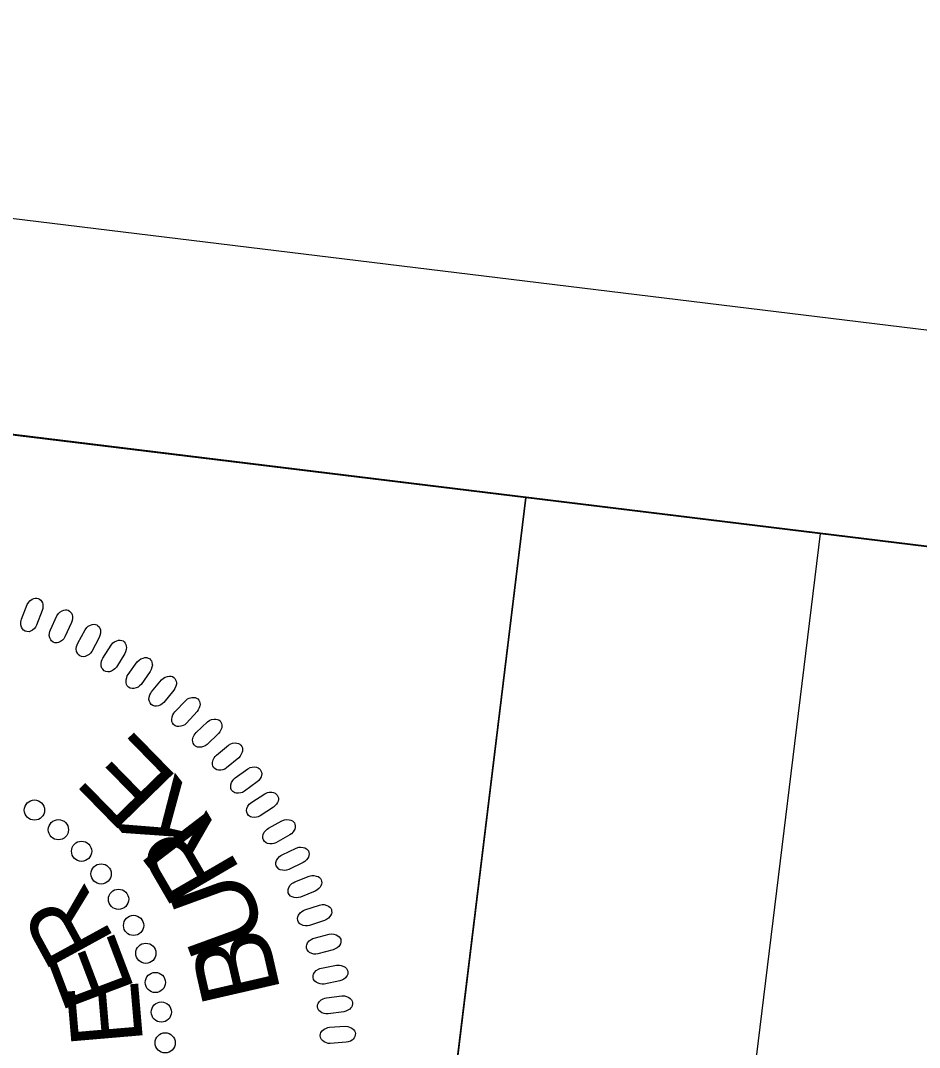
# Model space of a CAD drawing. Extents: x 480792 to 482083, y 490046 to 491850.
# Drawn here: x 481125.1 to 481196.3, y 491768.8 to 491850.2 of the extents above; entities that cross this region are included whole.
import ezdxf

# ---------------------------------------------------------------- set-up
doc = ezdxf.new("R2010")
doc.units = 0
for name, color, linetype in [('Sheet PE Seal Cell', 7, 'Continuous'), ('Sheet Plan CELL', 7, 'Continuous'), ('Sheet Plot Border Outside CELL', 7, 'Continuous'), ('Sheet Sticker Exception Certification CELL', 7, 'Continuous')]:
    doc.layers.add(name, color=color, linetype=linetype)

msp = doc.modelspace()

# ---------------------------------------------------------------- linework, layer by layer
at = {"layer": 'Sheet PE Seal Cell'}
for points in [[(481125.185, 491802.736), (481125.632, 491803.878), (481125.747, 491804.069), (481125.846, 491804.18), (481126.013, 491804.297), (481126.143, 491804.363), (481126.277, 491804.397), (481126.388, 491804.396), (481126.5, 491804.373), (481126.597, 491804.315), (481126.698, 491804.242), (481126.774, 491804.149), (481126.834, 491804.018), (481126.861, 491803.922), (481126.869, 491803.758), (481126.86, 491803.569), (481126.823, 491803.412), (481126.371, 491802.239), (481126.288, 491802.089), (481126.196, 491801.976), (481126.054, 491801.86), (481125.899, 491801.771), (481125.78, 491801.732), (481125.611, 491801.734), (481125.464, 491801.769), (481125.34, 491801.861), (481125.261, 491801.946), (481125.178, 491802.085), (481125.129, 491802.286), (481125.132, 491802.479), (481125.152, 491802.609)], [(481127.464, 491801.88), (481127.983, 491802.993), (481128.109, 491803.176), (481128.215, 491803.281), (481128.389, 491803.387), (481128.523, 491803.445), (481128.659, 491803.47), (481128.77, 491803.462), (481128.88, 491803.433), (481128.973, 491803.367), (481129.069, 491803.289), (481129.139, 491803.192), (481129.191, 491803.056), (481129.212, 491802.959), (481129.209, 491802.795), (481129.188, 491802.607), (481129.141, 491802.453), (481128.617, 491801.311), (481128.525, 491801.167), (481128.425, 491801.059), (481128.277, 491800.952), (481128.116, 491800.873), (481127.995, 491800.841), (481127.827, 491800.854), (481127.683, 491800.899), (481127.565, 491800.998), (481127.491, 491801.088), (481127.417, 491801.231), (481127.381, 491801.436), (481127.396, 491801.627), (481127.423, 491801.757)], [(481129.629, 491800.809), (481130.216, 491801.886), (481130.353, 491802.061), (481130.466, 491802.159), (481130.646, 491802.254), (481130.784, 491802.304), (481130.92, 491802.32), (481131.031, 491802.305), (481131.139, 491802.269), (481131.228, 491802.198), (481131.319, 491802.114), (481131.382, 491802.012), (481131.426, 491801.874), (481131.441, 491801.775), (481131.428, 491801.612), (481131.395, 491801.425), (481131.338, 491801.275), (481130.743, 491800.168), (481130.642, 491800.03), (481130.536, 491799.929), (481130.381, 491799.832), (481130.216, 491799.762), (481130.092, 491799.738), (481129.926, 491799.761), (481129.785, 491799.815), (481129.673, 491799.922), (481129.605, 491800.016), (481129.541, 491800.164), (481129.518, 491800.37), (481129.544, 491800.561), (481129.58, 491800.688)], [(481131.619, 491799.637), (481132.272, 491800.675), (481132.421, 491800.841), (481132.539, 491800.932), (481132.725, 491801.015), (481132.865, 491801.057), (481133.003, 491801.064), (481133.112, 491801.042), (481133.218, 491800.999), (481133.302, 491800.923), (481133.387, 491800.833), (481133.444, 491800.727), (481133.479, 491800.587), (481133.488, 491800.488), (481133.465, 491800.325), (481133.42, 491800.142), (481133.354, 491799.995), (481132.691, 491798.927), (481132.582, 491798.795), (481132.469, 491798.701), (481132.308, 491798.614), (481132.139, 491798.556), (481132.015, 491798.54), (481131.85, 491798.573), (481131.712, 491798.636), (481131.607, 491798.749), (481131.545, 491798.847), (481131.49, 491798.999), (481131.48, 491799.206), (481131.519, 491799.394), (481131.562, 491799.519)], [(481133.623, 491798.336), (481134.341, 491799.331), (481134.499, 491799.487), (481134.623, 491799.57), (481134.814, 491799.642), (481134.957, 491799.674), (481135.094, 491799.673), (481135.202, 491799.644), (481135.305, 491799.595), (481135.385, 491799.513), (481135.464, 491799.419), (481135.513, 491799.31), (481135.54, 491799.167), (481135.542, 491799.068), (481135.509, 491798.907), (481135.452, 491798.726), (481135.378, 491798.584), (481134.649, 491797.559), (481134.532, 491797.435), (481134.414, 491797.348), (481134.248, 491797.272), (481134.075, 491797.223), (481133.95, 491797.216), (481133.788, 491797.259), (481133.654, 491797.33), (481133.556, 491797.45), (481133.501, 491797.552), (481133.456, 491797.707), (481133.458, 491797.914), (481133.509, 491798.1), (481133.56, 491798.222)], [(481135.483, 491796.963), (481136.261, 491797.912), (481136.429, 491798.057), (481136.558, 491798.133), (481136.752, 491798.192), (481136.897, 491798.216), (481137.035, 491798.206), (481137.14, 491798.17), (481137.24, 491798.114), (481137.314, 491798.028), (481137.388, 491797.929), (481137.43, 491797.816), (481137.448, 491797.673), (481137.444, 491797.573), (481137.4, 491797.415), (481137.333, 491797.238), (481137.249, 491797.1), (481136.457, 491796.124), (481136.332, 491796.008), (481136.209, 491795.929), (481136.039, 491795.862), (481135.863, 491795.825), (481135.738, 491795.825), (481135.578, 491795.878), (481135.45, 491795.958), (481135.36, 491796.084), (481135.311, 491796.189), (481135.275, 491796.346), (481135.291, 491796.553), (481135.353, 491796.735), (481135.412, 491796.854)], [(481137.319, 491795.368), (481138.155, 491796.265), (481138.332, 491796.4), (481138.465, 491796.468), (481138.663, 491796.515), (481138.809, 491796.529), (481138.946, 491796.511), (481139.049, 491796.469), (481139.144, 491796.407), (481139.213, 491796.316), (481139.28, 491796.212), (481139.316, 491796.098), (481139.324, 491795.953), (481139.314, 491795.854), (481139.261, 491795.698), (481139.182, 491795.526), (481139.09, 491795.394), (481138.239, 491794.47), (481138.107, 491794.361), (481137.979, 491794.29), (481137.805, 491794.234), (481137.627, 491794.208), (481137.502, 491794.216), (481137.346, 491794.279), (481137.223, 491794.367), (481137.141, 491794.498), (481137.098, 491794.606), (481137.073, 491794.766), (481137.101, 491794.971), (481137.175, 491795.148), (481137.241, 491795.263)], [(481139.015, 491793.746), (481139.906, 491794.589), (481140.091, 491794.712), (481140.228, 491794.771), (481140.429, 491794.806), (481140.575, 491794.811), (481140.71, 491794.784), (481140.811, 491794.735), (481140.902, 491794.667), (481140.964, 491794.572), (481141.025, 491794.465), (481141.054, 491794.348), (481141.053, 491794.203), (481141.036, 491794.105), (481140.974, 491793.953), (481140.885, 491793.787), (481140.784, 491793.661), (481139.877, 491792.791), (481139.738, 491792.691), (481139.605, 491792.628), (481139.429, 491792.584), (481139.25, 491792.569), (481139.125, 491792.585), (481138.973, 491792.657), (481138.857, 491792.753), (481138.783, 491792.889), (481138.747, 491792.999), (481138.732, 491793.159), (481138.773, 491793.363), (481138.857, 491793.536), (481138.931, 491793.646)], [(481140.619, 491791.944), (481141.562, 491792.729), (481141.754, 491792.841), (481141.895, 491792.891), (481142.097, 491792.913), (481142.243, 491792.908), (481142.376, 491792.873), (481142.474, 491792.819), (481142.561, 491792.745), (481142.618, 491792.646), (481142.671, 491792.535), (481142.693, 491792.417), (481142.682, 491792.272), (481142.66, 491792.175), (481142.588, 491792.028), (481142.488, 491791.867), (481142.38, 491791.747), (481141.42, 491790.937), (481141.275, 491790.846), (481141.138, 491790.791), (481140.959, 491790.758), (481140.781, 491790.754), (481140.657, 491790.778), (481140.51, 491790.859), (481140.399, 491790.963), (481140.334, 491791.103), (481140.306, 491791.215), (481140.3, 491791.377), (481140.354, 491791.576), (481140.449, 491791.744), (481140.529, 491791.849)], [(481142.105, 491790.138), (481143.095, 491790.863), (481143.294, 491790.963), (481143.438, 491791.003), (481143.641, 491791.013), (481143.787, 491790.999), (481143.917, 491790.955), (481144.011, 491790.895), (481144.094, 491790.816), (481144.144, 491790.714), (481144.19, 491790.6), (481144.204, 491790.48), (481144.185, 491790.337), (481144.156, 491790.241), (481144.075, 491790.099), (481143.966, 491789.944), (481143.85, 491789.832), (481142.841, 491789.083), (481142.691, 491789.001), (481142.551, 491788.955), (481142.37, 491788.933), (481142.191, 491788.941), (481142.069, 491788.973), (481141.928, 491789.063), (481141.824, 491789.173), (481141.768, 491789.316), (481141.746, 491789.43), (481141.751, 491789.592), (481141.817, 491789.788), (481141.923, 491789.949), (481142.009, 491790.049)], [(481143.413, 491788.233), (481144.447, 491788.894), (481144.651, 491788.981), (481144.797, 491789.012), (481145.001, 491789.01), (481145.145, 491788.987), (481145.273, 491788.935), (481145.363, 491788.869), (481145.44, 491788.785), (481145.483, 491788.68), (481145.523, 491788.563), (481145.529, 491788.443), (481145.501, 491788.301), (481145.467, 491788.207), (481145.377, 491788.07), (481145.257, 491787.923), (481145.136, 491787.818), (481144.081, 491787.134), (481143.926, 491787.062), (481143.784, 491787.025), (481143.602, 491787.014), (481143.424, 491787.033), (481143.304, 491787.072), (481143.169, 491787.172), (481143.071, 491787.287), (481143.025, 491787.434), (481143.01, 491787.55), (481143.026, 491787.711), (481143.104, 491787.902), (481143.219, 491788.056), (481143.312, 491788.151)], [(481144.736, 491786.151), (481145.809, 491786.746), (481146.019, 491786.819), (481146.166, 491786.843), (481146.369, 491786.826), (481146.512, 491786.794), (481146.637, 491786.735), (481146.722, 491786.663), (481146.793, 491786.574), (481146.83, 491786.467), (481146.862, 491786.348), (481146.862, 491786.227), (481146.824, 491786.087), (481146.784, 491785.996), (481146.685, 491785.864), (481146.557, 491785.725), (481146.429, 491785.628), (481145.334, 491785.012), (481145.174, 491784.95), (481145.031, 491784.922), (481144.848, 491784.922), (481144.671, 491784.952), (481144.554, 491784.999), (481144.426, 491785.107), (481144.336, 491785.228), (481144.298, 491785.378), (481144.291, 491785.494), (481144.316, 491785.653), (481144.407, 491785.84), (481144.531, 491785.987), (481144.63, 491786.075)], [(481145.819, 491784.06), (481146.927, 491784.587), (481147.141, 491784.647), (481147.29, 491784.66), (481147.491, 491784.632), (481147.632, 491784.591), (481147.752, 491784.524), (481147.833, 491784.447), (481147.9, 491784.354), (481147.929, 491784.244), (481147.954, 491784.123), (481147.945, 491784.003), (481147.9, 491783.866), (481147.853, 491783.777), (481147.747, 491783.652), (481147.61, 491783.521), (481147.476, 491783.432), (481146.344, 491782.887), (481146.181, 491782.834), (481146.036, 491782.815), (481145.853, 491782.827), (481145.679, 491782.868), (481145.566, 491782.922), (481145.444, 491783.038), (481145.362, 491783.165), (481145.333, 491783.317), (481145.334, 491783.433), (481145.369, 491783.59), (481145.471, 491783.771), (481145.604, 491783.909), (481145.709, 491783.991)], [(481146.821, 491781.904), (481147.96, 491782.36), (481148.177, 491782.407), (481148.327, 491782.41), (481148.526, 491782.369), (481148.664, 491782.32), (481148.779, 491782.245), (481148.855, 491782.163), (481148.916, 491782.066), (481148.939, 491781.955), (481148.955, 491781.833), (481148.939, 491781.714), (481148.885, 491781.58), (481148.833, 491781.494), (481148.719, 491781.376), (481148.575, 491781.253), (481148.435, 491781.174), (481147.271, 491780.7), (481147.106, 491780.657), (481146.959, 491780.647), (481146.778, 491780.671), (481146.607, 491780.723), (481146.496, 491780.784), (481146.382, 491780.907), (481146.308, 491781.039), (481146.29, 491781.192), (481146.297, 491781.308), (481146.342, 491781.463), (481146.455, 491781.637), (481146.597, 491781.767), (481146.706, 491781.842)], [(481147.622, 491779.689), (481148.788, 491780.072), (481149.007, 491780.105), (481149.156, 491780.1), (481149.353, 491780.046), (481149.487, 491779.988), (481149.598, 491779.906), (481149.669, 491779.82), (481149.722, 491779.719), (481149.738, 491779.607), (481149.747, 491779.483), (481149.724, 491779.365), (481149.661, 491779.235), (481149.605, 491779.153), (481149.484, 491779.042), (481149.331, 491778.93), (481149.187, 491778.858), (481147.995, 491778.459), (481147.827, 491778.427), (481147.68, 491778.426), (481147.501, 491778.461), (481147.334, 491778.524), (481147.227, 491778.592), (481147.121, 491778.721), (481147.056, 491778.858), (481147.047, 491779.012), (481147.062, 491779.127), (481147.116, 491779.279), (481147.24, 491779.445), (481147.39, 491779.566), (481147.504, 491779.634)], [(481148.364, 491777.455), (481149.551, 491777.764), (481149.772, 491777.783), (481149.921, 491777.768), (481150.113, 491777.702), (481150.244, 491777.636), (481150.349, 491777.547), (481150.414, 491777.457), (481150.462, 491777.353), (481150.47, 491777.24), (481150.472, 491777.116), (481150.441, 491777), (481150.37, 491776.874), (481150.308, 491776.795), (481150.18, 491776.692), (481150.022, 491776.59), (481149.873, 491776.527), (481148.659, 491776.203), (481148.49, 491776.182), (481148.343, 491776.19), (481148.166, 491776.237), (481148.003, 491776.31), (481147.901, 491776.384), (481147.803, 491776.52), (481147.746, 491776.661), (481147.747, 491776.815), (481147.77, 491776.929), (481147.834, 491777.077), (481147.967, 491777.235), (481148.124, 491777.346), (481148.242, 491777.407)], [(481148.938, 491775.075), (481150.142, 491775.309), (481150.364, 491775.315), (481150.512, 491775.291), (481150.7, 491775.213), (481150.826, 491775.138), (481150.926, 491775.043), (481150.985, 491774.948), (481151.025, 491774.841), (481151.028, 491774.728), (481151.021, 491774.605), (481150.983, 491774.491), (481150.904, 491774.369), (481150.838, 491774.295), (481150.704, 491774.201), (481150.539, 491774.107), (481150.386, 491774.055), (481149.155, 491773.807), (481148.984, 491773.797), (481148.838, 491773.815), (481148.665, 491773.872), (481148.507, 491773.955), (481148.409, 491774.036), (481148.32, 491774.179), (481148.272, 491774.321), (481148.283, 491774.475), (481148.312, 491774.588), (481148.385, 491774.732), (481148.529, 491774.881), (481148.693, 491774.982), (481148.814, 491775.036)], [(481149.327, 491772.719), (481150.544, 491772.877), (481150.765, 491772.868), (481150.911, 491772.835), (481151.094, 491772.745), (481151.215, 491772.663), (481151.309, 491772.562), (481151.362, 491772.464), (481151.396, 491772.355), (481151.391, 491772.242), (481151.376, 491772.119), (481151.331, 491772.007), (481151.245, 491771.891), (481151.174, 491771.821), (481151.034, 491771.735), (481150.864, 491771.653), (481150.708, 491771.61), (481149.464, 491771.44), (481149.292, 491771.44), (481149.148, 491771.467), (481148.978, 491771.535), (481148.826, 491771.628), (481148.734, 491771.715), (481148.654, 491771.862), (481148.615, 491772.008), (481148.636, 491772.161), (481148.672, 491772.272), (481148.753, 491772.411), (481148.907, 491772.551), (481149.076, 491772.641), (481149.2, 491772.688)], [(481149.584, 491770.385), (481150.808, 491770.466), (481151.029, 491770.444), (481151.172, 491770.401), (481151.349, 491770.301), (481151.465, 491770.21), (481151.552, 491770.104), (481151.599, 491770.002), (481151.626, 491769.891), (481151.613, 491769.779), (481151.591, 491769.657), (481151.539, 491769.549), (481151.446, 491769.438), (481151.371, 491769.373), (481151.226, 491769.296), (481151.051, 491769.224), (481150.893, 491769.191), (481149.64, 491769.1), (481149.469, 491769.111), (481149.326, 491769.147), (481149.162, 491769.225), (481149.015, 491769.327), (481148.928, 491769.419), (481148.859, 491769.572), (481148.829, 491769.72), (481148.859, 491769.871), (481148.901, 491769.979), (481148.992, 491770.113), (481149.153, 491770.243), (481149.329, 491770.323), (481149.455, 491770.361)]]:
    msp.add_lwpolyline(points, close=True, dxfattribs=at)
for centre in [(481126.202, 491787.596), (481128.099, 491786.04), (481129.936, 491784.331), (481131.483, 491782.537), (481132.865, 491780.526), (481134.056, 491778.455), (481135.03, 491776.25), (481135.778, 491773.935), (481136.253, 491771.591), (481136.556, 491769.147)]:
    msp.add_circle(centre, 0.801, dxfattribs=at)
at = {"layer": 'Sheet Plan CELL'}
for points in [[(481016.186, 491830.584), (480834.326, 490341.611), (481876.581, 490214.312), (482058.438, 491703.26)], [(481041.344, 491726.742), (481053.454, 491825.994), (481165.138, 491812.366), (481153.027, 491713.102)], [(481876.581, 490214.312), (480834.348, 490341.583), (480991.917, 491631.986), (481140.874, 491613.805), (481165.138, 491812.366), (482058.438, 491703.26)]]:
    msp.add_lwpolyline(points, close=True, dxfattribs=at)
at = {"layer": 'Sheet Plot Border Outside CELL'}
msp.add_lwpolyline([(481878.743, 490046.324), (482082.845, 491717.405), (480995.922, 491850.16), (480791.82, 490179.078)], close=True, dxfattribs=at)
at = {"layer": 'Sheet Sticker Exception Certification CELL'}
for p, q in [((481140.874, 491613.805), (481165.126, 491812.367)), ((481140.874, 491613.805), (481165.126, 491812.367)), ((481165.138, 491812.366), (481188.465, 491809.517)), ((481165.138, 491812.366), (481188.465, 491809.517)), ((481188.453, 491809.518), (481164.201, 491610.956)), ((481188.453, 491809.518), (481164.201, 491610.956))]:
    msp.add_line(p, q, dxfattribs=at)

# ---------------------------------------------------------------- texts
at = {"layer": 'Sheet PE Seal Cell'}
for s, height, rotation, p in [('E', 6.236, 134.30477, (481137.714, 491790.016)), ('K', 6.236, 127.45912, (481140.651, 491786.226)), ('R', 6.236, 120.18409, (481142.633, 491782.729)), ('U', 6.236, 110.08424, (481144.687, 491777.537)), ('R', 5.669, 118.70007, (481132.61, 491777.311)), ('B', 6.236, 102.9674, (481145.745, 491773.157)), ('E', 5.669, 110.76028, (481134.199, 491773.308)), ('E', 5.669, 94.88068, (481134.82, 491769.132))]:
    msp.add_text(s, height=height, rotation=rotation, dxfattribs=at).set_placement(p)

doc.saveas('drawing.dxf')
